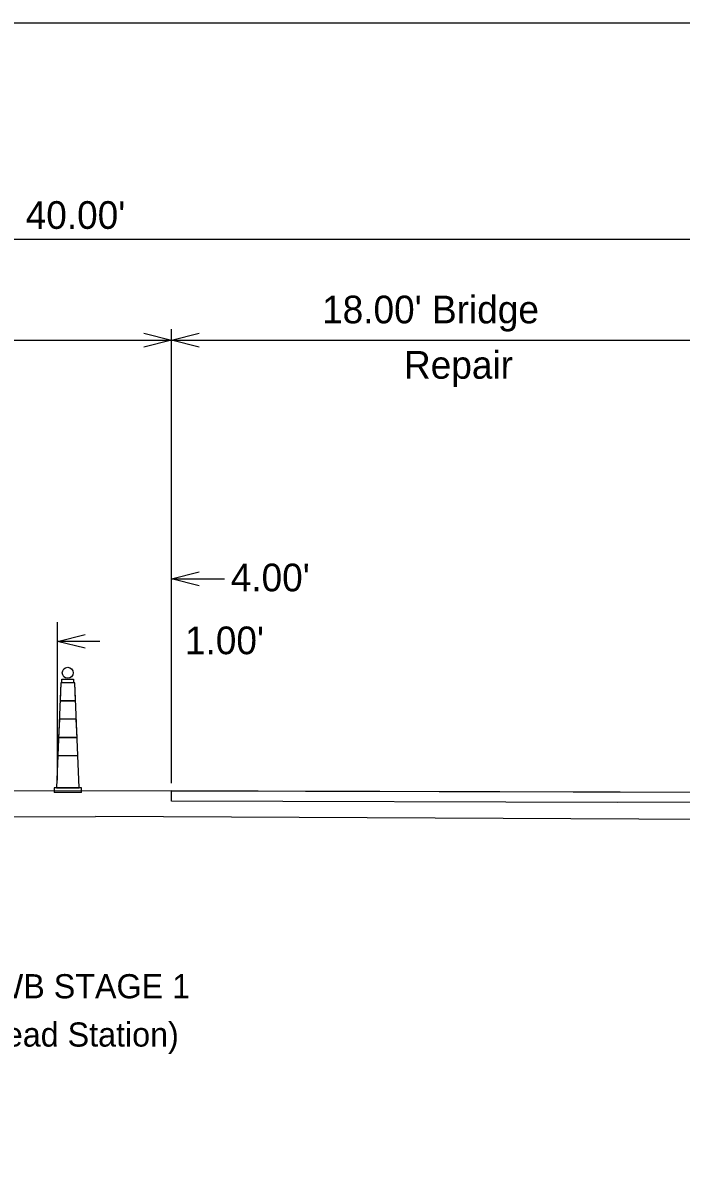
# Model space of a CAD drawing. Extents: x 8410 to 81668, y 7924 to 12712.
# Drawn here: x 15241 to 15781, y 9002 to 9944 of the extents above; entities that cross this region are included whole.
import ezdxf

# ---------------------------------------------------------------- set-up
doc = ezdxf.new("R2010")
doc.units = 0
for name, color, linetype in [('dsnCellElements', 7, 'Continuous'), ('Level 2', 7, 'Continuous'), ('Level 3', 7, 'Continuous'), ('SheetBorder', 7, 'Continuous')]:
    doc.layers.add(name, color=color, linetype=linetype)

msp = doc.modelspace()

# ---------------------------------------------------------------- linework, layer by layer
at = {"layer": 'dsnCellElements'}
for p, q in [((15271.73, 9402.95), (15267.98, 9316.7)), ((15271.73, 9402.95), (15271.08, 9387.95)), ((15282.98, 9402.95), (15271.73, 9402.95)), ((15282.98, 9402.95), (15271.73, 9402.95)), ((15286.73, 9316.7), (15282.98, 9402.95)), ((15283.63, 9387.95), (15282.98, 9402.95)), ((15283.63, 9387.95), (15271.08, 9387.95)), ((15271.08, 9387.95), (15283.63, 9387.95)), ((15270.42, 9372.95), (15269.77, 9357.95)), ((15284.28, 9372.95), (15270.42, 9372.95)), ((15284.28, 9372.95), (15270.42, 9372.95)), ((15284.94, 9357.95), (15284.28, 9372.95)), ((15284.94, 9357.95), (15269.77, 9357.95)), ((15269.77, 9357.95), (15284.94, 9357.95)), ((15269.12, 9342.95), (15267.98, 9316.7)), ((15285.59, 9342.95), (15269.12, 9342.95)), ((15285.59, 9342.95), (15269.12, 9342.95)), ((15286.73, 9316.7), (15285.59, 9342.95)), ((15288.6, 9316.7), (15266.1, 9316.7)), ((15266.1, 9316.7), (15266.1, 9312.95)), ((15288.6, 9312.95), (15266.1, 9312.95)), ((15267.98, 9316.7), (15286.73, 9316.7)), ((15288.6, 9312.95), (15288.6, 9316.7))]:
    msp.add_line(p, q, dxfattribs=at)
msp.add_lwpolyline([(15272.48, 9405.95), (15282.08, 9405.95), (15282.08, 9402.95), (15272.48, 9402.95)], close=True, dxfattribs=at)
msp.add_circle((15277.28, 9411.05), 4.5, dxfattribs=at)
at = {"layer": 'Level 2'}
for p, q in [((14675.73, 9766.62), (15924.32, 9766.62)), ((15362.45, 9320.53), (15362.45, 9692.88)), ((14675.73, 9683.9), (15362.45, 9683.9)), ((15362.45, 9683.9), (15924.32, 9683.9)), ((15362.45, 9488.08), (15405.9, 9488.08)), ((15268.81, 9323.08), (15268.81, 9452.51)), ((15303.5, 9436.86), (15268.81, 9436.86)), ((14734.51, 9290.34), (15300.02, 9293.26)), ((15865.54, 9290.34), (15300.02, 9293.26))]:
    msp.add_line(p, q, dxfattribs=at)
for points in [[(15339.74, 9689.58), (15362.45, 9683.9), (15339.74, 9678.23)], [(15385.16, 9678.23), (15362.45, 9683.9), (15385.16, 9689.58)], [(15385.16, 9482.4), (15362.45, 9488.08), (15385.16, 9493.76)], [(15291.52, 9431.19), (15268.81, 9436.86), (15291.52, 9442.54)]]:
    msp.add_lwpolyline(points, dxfattribs=at)
at = {"layer": 'Level 3'}
for p, q in [((15362.45, 9314.37), (14638.81, 9312.64)), ((15362.45, 9314.37), (15961.24, 9312.64)), ((15362.45, 9305.76), (15362.45, 9313.81)), ((15728.34, 9304.65), (15362.45, 9305.76))]:
    msp.add_line(p, q, dxfattribs=at)
for points in [[(15362.45, 9313.81), (15362.45, 9313.81), (15362.45, 9314.37), (15364.5, 9314.36), (15377.27, 9314.32), (15386.59, 9314.3), (15433.64, 9314.16), (15498.92, 9313.97), (15533.42, 9313.87), (15730.54, 9313.31)], [(15730.54, 9313.31), (15924.32, 9312.74), (15924.28, 9305.05), (15728.34, 9304.65)]]:
    msp.add_lwpolyline(points, dxfattribs=at)
at = {"layer": 'SheetBorder'}
msp.add_lwpolyline([(13732.52, 9944.02), (16867.53, 9944.02), (16867.53, 7924.02), (13732.52, 7924.02)], close=True, dxfattribs=at)

# ---------------------------------------------------------------- texts
at = {"layer": 'Level 2'}
for s, height, p in [("40.00'", 22.709, (15242.76, 9775.15)), ("18.00' Bridge", 22.7091, (15486.02, 9697.67)), ('Repair', 22.709, (15553.26, 9652.26)), ("4.00'", 22.709, (15411.05, 9477.89)), ("1.00'", 22.709, (15373.48, 9426.3)), ('US 20 WB STAGE 1', 19.8, (15134.86, 9144.11)), ('(Looking Ahead Station)', 19.8, (15084.35, 9104.51))]:
    msp.add_text(s, height=height, dxfattribs=at).set_placement(p)

doc.saveas('drawing.dxf')
